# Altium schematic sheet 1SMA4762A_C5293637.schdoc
size 127 x 101 mm
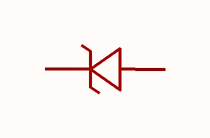
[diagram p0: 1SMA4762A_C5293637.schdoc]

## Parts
D?  1sma4762a_c5293637  [SMAG_L4.3-W2.6-LS5.3-RD]  (value not drawn)

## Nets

Not connected (* = marked no-connect by the designer): D? 1(K) 2(A)

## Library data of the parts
D? = 1sma4762a_c5293637: 稳压值(标称值):82V;稳压值(范围):-;耗散功率(Pd):1W;; Manufacturer: CJ(江苏长电/长晶); AddInBom: yes; ModelId: 3cd8680d946b497db8ea5837610a9736; ModelTransform: 208.661,102.362,0,0,0,0,0,0,0; Zener Voltage(Nom): 82V; Reverse Leakage Current (Ir): 100nA; Pd - Power Dissipation: 1W; Impedance(Zzt): 200Ω; Impedance(Zzk): 3kΩ; Operating Junction Temperature Range: -55℃~+150℃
